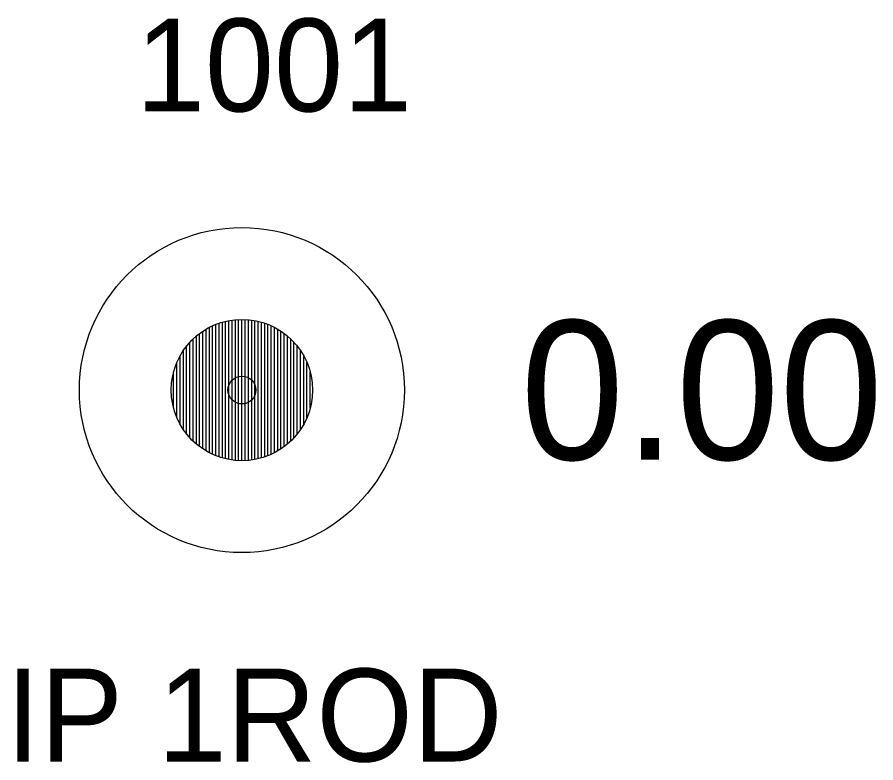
# Model space of a CAD drawing. Extents: x 2259948 to 2261336, y 1064647 to 1065986.
# Drawn here: x 2259955.94 to 2259965.19, y 1065874.92 to 1065882.95 of the extents above; entities that cross this region are included whole.
import ezdxf

# ---------------------------------------------------------------- set-up
doc = ezdxf.new("R2010")
doc.units = 0
for name, color, linetype in [('RD_EX_DV_Prop_txCode', 7, 'Continuous'), ('RD_EX_DV_PropPin', 7, 'Continuous'), ('RD_EX_TX_DV_Prop_ELEV', 7, 'Continuous'), ('RD_SMD_Locator', 7, 'Continuous')]:
    doc.layers.add(name, color=color, linetype=linetype)

msp = doc.modelspace()

# ---------------------------------------------------------------- linework, layer by layer
at = {"layer": 'RD_EX_DV_PropPin'}
for p, q in [((2259958.2201, 1065878.1824), (2259958.2201, 1065879.6784)), ((2259958.2551, 1065878.1767), (2259958.2551, 1065879.6841)), ((2259958.2902, 1065878.1726), (2259958.2902, 1065879.6882)), ((2259958.3252, 1065878.1702), (2259958.3252, 1065879.6906)), ((2259958.3602, 1065878.1694), (2259958.3602, 1065879.6914)), ((2259958.3952, 1065878.1702), (2259958.3952, 1065879.6906)), ((2259958.4302, 1065878.1726), (2259958.4302, 1065879.6882)), ((2259958.4652, 1065878.1767), (2259958.4652, 1065879.6841)), ((2259958.5002, 1065878.1824), (2259958.5002, 1065879.6784)), ((2259957.975, 1065878.274), (2259957.975, 1065879.5868)), ((2259958.01, 1065878.2547), (2259958.01, 1065879.6061)), ((2259958.0451, 1065878.2377), (2259958.0451, 1065879.6231)), ((2259958.0801, 1065878.2228), (2259958.0801, 1065879.638)), ((2259958.1151, 1065878.2099), (2259958.1151, 1065879.6509)), ((2259958.1501, 1065878.199), (2259958.1501, 1065879.6618)), ((2259958.1851, 1065878.1898), (2259958.1851, 1065879.671)), ((2259958.5352, 1065878.1898), (2259958.5352, 1065879.671)), ((2259958.5703, 1065878.199), (2259958.5703, 1065879.6618)), ((2259958.6053, 1065878.2099), (2259958.6053, 1065879.6509)), ((2259958.6403, 1065878.2228), (2259958.6403, 1065879.638)), ((2259958.6753, 1065878.2377), (2259958.6753, 1065879.6231)), ((2259958.7103, 1065878.2547), (2259958.7103, 1065879.6061)), ((2259958.7453, 1065878.274), (2259958.7453, 1065879.5868)), ((2259957.87, 1065878.3483), (2259957.87, 1065879.5125)), ((2259957.905, 1065878.3205), (2259957.905, 1065879.5403)), ((2259957.94, 1065878.2959), (2259957.94, 1065879.5649)), ((2259958.7803, 1065878.2959), (2259958.7803, 1065879.5649)), ((2259958.8154, 1065878.3205), (2259958.8154, 1065879.5403)), ((2259958.8504, 1065878.3483), (2259958.8504, 1065879.5125)), ((2259957.7649, 1065878.4562), (2259957.7649, 1065879.4046)), ((2259957.8, 1065878.4153), (2259957.8, 1065879.4455)), ((2259957.835, 1065878.3797), (2259957.835, 1065879.4811)), ((2259958.8854, 1065878.3797), (2259958.8854, 1065879.4811)), ((2259958.9204, 1065878.4153), (2259958.9204, 1065879.4455)), ((2259958.9554, 1065878.4562), (2259958.9554, 1065879.4046)), ((2259957.7299, 1065878.5039), (2259957.7299, 1065879.3569)), ((2259958.9904, 1065878.5039), (2259958.9904, 1065879.3569)), ((2259957.6599, 1065878.6325), (2259957.6599, 1065879.2283)), ((2259957.6949, 1065878.5609), (2259957.6949, 1065879.2999)), ((2259959.0254, 1065878.5609), (2259959.0254, 1065879.2999)), ((2259959.0605, 1065878.6325), (2259959.0605, 1065879.2283)), ((2259957.6249, 1065878.7342), (2259957.6249, 1065879.1266)), ((2259959.0955, 1065878.7342), (2259959.0955, 1065879.1266))]:
    msp.add_line(p, q, dxfattribs=at)
for radius in [1.75, 0.761]:
    msp.add_circle((2259958.3602, 1065878.9304), radius, dxfattribs=at)
at = {"layer": 'RD_SMD_Locator'}
msp.add_circle((2259958.3602, 1065878.9304), 0.15, dxfattribs=at)

# ---------------------------------------------------------------- texts
at = {"layer": 'RD_EX_DV_Prop_txCode'}
for s, p in [('1001', (2259957.2185, 1065881.9304)), ('IP 1ROD', (2259955.8169, 1065874.9304))]:
    msp.add_text(s, height=1, dxfattribs=at).set_placement(p)
at = {"layer": 'RD_EX_TX_DV_Prop_ELEV'}
msp.add_text('0.00', height=1.5, dxfattribs=at).set_placement((2259961.3602, 1065878.1804))

doc.saveas('drawing.dxf')
